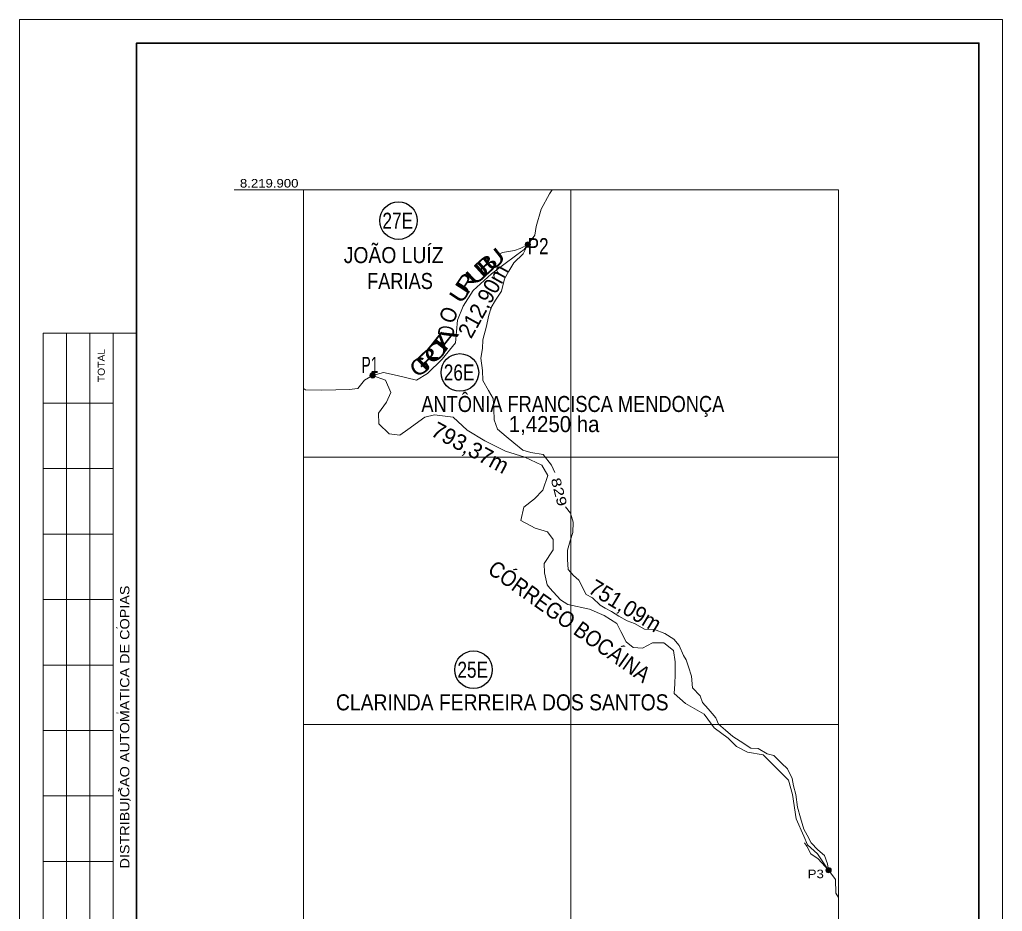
# Model space of a CAD drawing. Extents: x 253235 to 254153, y 8218760 to 8220059.
# Drawn here: x 253235 to 254153, y 8219225 to 8220059 of the extents above; entities that cross this region are included whole.
import ezdxf
from ezdxf.enums import TextEntityAlignment as Align

# ---------------------------------------------------------------- set-up
doc = ezdxf.new("R2010")
doc.units = 0
doc.header["$LTSCALE"] = 4.7
for name, color, linetype, lineweight in [('1', 7, 'Continuous', 13), ('2', 7, 'Continuous', 13), ('3', 7, 'Continuous', 13), ('34', 7, 'Continuous', 25), ('37', 7, 'Continuous', 13), ('6', 7, 'Continuous', 13)]:
    doc.layers.add(name, color=color, linetype=linetype, lineweight=lineweight)
for name, color, linetype in [('31', 7, 'Continuous'), ('32', 7, 'Continuous'), ('33', 7, 'Continuous'), ('40', 7, 'Continuous')]:
    doc.layers.add(name, color=color, linetype=linetype)

msp = doc.modelspace()

# ---------------------------------------------------------------- hatches: boundary and pattern name
at = {"layer": '37'}
for points in [[(253712.175, 8219848.903, 1), (253707.175, 8219848.903, 1)], [(253567.05, 8219726.55, 1), (253562.05, 8219726.55, 1)], [(253993.305, 8219263.695, 1), (253988.305, 8219263.695, 1)]]:
    msp.add_hatch(color=256, dxfattribs=at).paths.add_polyline_path(points)

# ---------------------------------------------------------------- linework, layer by layer
at = {"layer": '1'}
for points in [[(253682.39, 8219839.93), (253685.96, 8219841.49), (253697.16, 8219843.28), (253702.54, 8219845.07), (253709.67, 8219848.9), (253705.22, 8219840.15), (253696.71, 8219831.64), (253691.78, 8219824.02), (253687.75, 8219816.85), (253685.01, 8219805.15), (253679.51, 8219797.02), (253675.28, 8219790.11), (253672.76, 8219781.57), (253671.12, 8219772.41), (253667.59, 8219759.73), (253667.15, 8219751.67), (253665.8, 8219742.71), (253667.15, 8219731.06), (253667.59, 8219721.66), (253672.97, 8219712.25), (253677.3, 8219704.87)], [(253677.3, 8219704.87), (253677.84, 8219694.95), (253678.06, 8219684.82), (253681.36, 8219676.17), (253689.47, 8219669.21), (253696.63, 8219663.31), (253704.84, 8219656.63), (253712.39, 8219654.24), (253724.04, 8219652.44), (253731.66, 8219642.59), (253734.77, 8219635.51)], [(253744.9, 8219603.58), (253749.47, 8219597.47), (253752.02, 8219589.12), (253751.68, 8219579.62), (253749.3, 8219571.84), (253746.68, 8219563.08), (253746.81, 8219554.29), (253747.44, 8219544.97), (253752.49, 8219539.33), (253757.41, 8219534.85), (253764.13, 8219521.41), (253769.96, 8219518.27), (253777.13, 8219511.55), (253782.05, 8219508.87), (253787.88, 8219505.73), (253794.6, 8219501.25), (253802.66, 8219496.77), (253809.38, 8219494.53), (253818.79, 8219489.15), (253828.19, 8219488.71), (253837.6, 8219485.12), (253846.11, 8219479.75), (253851.04, 8219473.92), (253855.07, 8219464.52), (253857.76, 8219460.48), (253860, 8219453.99), (253862.69, 8219445.03), (253863.59, 8219434.28), (253870.75, 8219426.66), (253872.99, 8219420.39), (253878.37, 8219414.57), (253881.95, 8219410.09), (253885.54, 8219406.05), (253888.01, 8219400.37), (253894.52, 8219394.72), (253901.25, 8219388.81), (253908.22, 8219384.2), (253918.24, 8219377.83), (253924.96, 8219377.38), (253933.47, 8219372.46), (253939.52, 8219370.89), (253946.69, 8219363.72), (253952.39, 8219358.31), (253956.78, 8219349.42), (253957.89, 8219342.66), (253960.13, 8219334.6), (253961.92, 8219322.51), (253964.61, 8219312.65), (253967.74, 8219301.9), (253970.76, 8219296.44), (253974.66, 8219289.37), (253980.82, 8219282.74), (253986.95, 8219277.41), (253989.69, 8219269.64), (253990.81, 8219263.69), (253980.99, 8219274.33), (253974.13, 8219279), (253970.43, 8219286.22), (253968.41, 8219289.11)]]:
    msp.add_lwpolyline(points, dxfattribs=at)
at = {"layer": '2'}
for points in [[(253500, 8219714.11), (253501.75, 8219712.98), (253516.36, 8219712.68), (253530.15, 8219713.11), (253542.59, 8219713.23), (253550.59, 8219714.36), (253556.96, 8219722.03), (253564.55, 8219726.55), (253576.53, 8219721.92), (253581.62, 8219710.57), (253577.38, 8219701.61), (253570, 8219691.21), (253570.43, 8219681.14), (253579.94, 8219671.96), (253589.94, 8219670.72)], [(253589.94, 8219670.72), (253597.46, 8219675.94), (253613.32, 8219687.48), (253622.37, 8219689.67), (253639.89, 8219687.34), (253652.92, 8219675.34), (253669.35, 8219665.22), (253688.84, 8219655.72), (253706.82, 8219650.16), (253722.86, 8219642.62), (253728.5, 8219632.95), (253723.64, 8219619.23), (253715.82, 8219611.09), (253706.01, 8219603.33), (253703.21, 8219590.9), (253716.55, 8219583.66), (253727.9, 8219580.14), (253733.26, 8219572.84), (253733.3, 8219563.3), (253724.8, 8219550.66), (253725.08, 8219541.88), (253727.64, 8219530.68), (253730.09, 8219527.51), (253740.25, 8219516.4), (253747.04, 8219512.11), (253767.41, 8219507.97), (253780.88, 8219501.97), (253792.88, 8219494.32), (253796.68, 8219487.08), (253801.57, 8219477.24), (253808.28, 8219472.08), (253816.87, 8219471.4), (253826.06, 8219476.39), (253836.73, 8219476.25), (253845.87, 8219469.06), (253847.49, 8219458.48), (253847.42, 8219446.83), (253847.06, 8219437.97), (253846.55, 8219428.9), (253857.19, 8219419.64), (253874.42, 8219409.7), (253883.98, 8219396.85), (253896.84, 8219387.06), (253904.75, 8219379.51), (253914.96, 8219374.18), (253929.58, 8219371.5), (253953.43, 8219347.88), (253956.96, 8219334.49), (253960.63, 8219311.78), (253967.8, 8219295.42), (253971.19, 8219287.36), (253980.41, 8219278.82), (253988.6, 8219266.7), (253997.26, 8219254.9), (253997.65, 8219242.24), (254000, 8219238.14)]]:
    msp.add_lwpolyline(points, dxfattribs=at)
at = {"layer": '3'}
for points in [[(253699.48, 8219839.21), (253706.19, 8219844.25), (253716.13, 8219857.52), (253717.32, 8219865.64), (253722.23, 8219881.9), (253729.93, 8219896.4), (253732.4, 8219900)], [(253564.55, 8219726.55), (253574.72, 8219729.2), (253587.46, 8219726.31), (253605.4, 8219722.05), (253615.96, 8219728.38), (253629.68, 8219741.53), (253641.99, 8219757.08), (253643.75, 8219778.16), (253649.12, 8219791.3), (253658.65, 8219805.91), (253675.75, 8219821.36), (253685.89, 8219829.35), (253699.48, 8219839.21)]]:
    msp.add_lwpolyline(points, dxfattribs=at)
at = {"layer": '34'}
for centre in [(253588.72, 8219871.241), (253646.086, 8219729.24), (253658.844, 8219451.204)]:
    msp.add_circle(centre, 17.6, dxfattribs=at)
at = {"layer": '37'}
for centre in [(253709.675, 8219848.903), (253564.55, 8219726.55), (253990.805, 8219263.695)]:
    msp.add_circle(centre, 2.5, dxfattribs=at)
at = {"layer": '6'}
for p, q in [((253435, 8219900), (254000, 8219900)), ((253500, 8219095), (253500, 8219900)), ((253750, 8219150), (253750, 8219900)), ((254000, 8219095), (254000, 8219900)), ((253256.41, 8219766.08), (253343.91, 8219766.08)), ((253256.41, 8219766.08), (253256.41, 8219022.38)), ((253278.31, 8219766.08), (253278.31, 8219022.38)), ((253300.11, 8219022.38), (253300.11, 8219766.08)), ((253322.01, 8219766.08), (253322.01, 8219022.38)), ((253256.41, 8219700.48), (253322.01, 8219700.48)), ((253500, 8219650), (254000, 8219650)), ((253256.41, 8219639.28), (253322.01, 8219639.28)), ((253256.41, 8219578.08), (253322.01, 8219578.08)), ((253256.41, 8219516.78), (253322.01, 8219516.78)), ((253326.01, 8219490.18), (253324.71, 8219490.68)), ((253256.41, 8219455.48), (253322.01, 8219455.48)), ((253326.51, 8219410.48), (253325.11, 8219410.88)), ((253256.41, 8219394.28), (253322.01, 8219394.28)), ((253500, 8219400), (254000, 8219400)), ((253256.41, 8219333.08), (253322.01, 8219333.08)), ((253337.11, 8219329.48), (253338.21, 8219328.88)), ((253256.41, 8219271.78), (253322.01, 8219271.78))]:
    msp.add_line(p, q, dxfattribs=at)
msp.add_lwpolyline([(253234.51, 8218759.88), (254153.31, 8218759.88), (254153.31, 8220059.28), (253234.51, 8220059.28)], close=True, dxfattribs=at)
at = {"layer": '6', "lineweight": 35}
msp.add_lwpolyline([(253343.91, 8218781.78), (254131.41, 8218781.78), (254131.41, 8220037.38), (253343.91, 8220037.38)], close=True, dxfattribs=at)
at = {"layer": '6'}
msp.add_spline([(253327.21, 8219337.28), (253326.91, 8219338.28), (253327.51, 8219338.88), (253327.71, 8219339.58), (253327.31, 8219340.38)], degree=3, dxfattribs=at)

# ---------------------------------------------------------------- texts
at = {"layer": '1', "width": 0.85}
msp.add_text('FARIAS', height=15, dxfattribs=at).set_placement((253590.075, 8219807.28), align=Align.CENTER)
at = {"layer": '1', "width": 1.35}
msp.add_text('829', height=9, rotation=284.747, dxfattribs=at).set_placement((253734.453, 8219616.355), align=Align.CENTER)
at = {"layer": '31', "width": 0.95}
msp.add_text('212,90m', height=15, rotation=60.902, dxfattribs=at).set_placement((253674.672, 8219792.468), align=Align.CENTER)
msp.add_text('1,4250 ha', height=15, dxfattribs=at).set_placement((253734.21, 8219673.46), align=Align.CENTER)
at = {"layer": '32'}
msp.add_text('793,37m', height=15, rotation=331.83, dxfattribs=at).set_placement((253652.309, 8219652.256), align=Align.CENTER)
at = {"layer": '32', "width": 0.95}
msp.add_text('751,09m', height=15, rotation=328.859, dxfattribs=at).set_placement((253796.836, 8219504.628), align=Align.CENTER)
at = {"layer": '33'}
for s, width, p in [('JOÃO LUÍZ', 0.9, (253584.185, 8219831.54)), ('ANTÔNIA FRANCISCA MENDONÇA', 0.85, (253751.71, 8219692.27)), ('CLARINDA FERREIRA DOS SANTOS', 0.9, (253685.735, 8219413.16))]:
    msp.add_text(s, height=15, dxfattribs=dict(at, width=width)).set_placement(p, align=Align.CENTER)
at = {"layer": '34', "width": 0.8}
for s, p in [('27E', (253587.98, 8219863.68)), ('26E', (253645.35, 8219721.73)), ('25E', (253658.1, 8219443.66))]:
    msp.add_text(s, height=15, dxfattribs=at).set_placement(p, align=Align.CENTER)
at = {"layer": '37'}
for s, height, width, p in [('P2', 15, 0.8, (253719.23, 8219839.88)), ('P1', 15, 0.65, (253562.015, 8219728.86)), ('P3', 8, 1.15, (253978.885, 8219256.16))]:
    msp.add_text(s, height=height, dxfattribs=dict(at, width=width)).set_placement(p, align=Align.CENTER)
at = {"layer": '40'}
for s, rotation, width, p in [('U', 38.237, 1.4, (253682.473, 8219829.192)), ('U', 42.098, 1.5, (253667.607, 8219816.697)), ('B', 42.098, 1.65, (253675.257, 8219823.617)), ('R', 56.884, 1.25, (253658.146, 8219808.802)), ('U', 56.884, 1.25, (253652.516, 8219800.162)), ('O', 67.771, 0.9, (253642.469, 8219780.293)), ('D', 85.227, 0.65, (253640.855, 8219767.576)), ('T', 51.633, 1.75, (253634.149, 8219750.405)), ('A', 51.633, 1.65, (253638.803, 8219756.27)), ('R', 43.785, 1.55, (253621.675, 8219736.626)), ('O', 43.785, 1.45, (253628.775, 8219743.436)), ('G', 30.94, 1.15, (253612.604, 8219728.694)), ('CÓRREGO BOCÁINA', 324.557, 0.9, (253744.191, 8219490.245))]:
    msp.add_text(s, height=15, rotation=rotation, dxfattribs=dict(at, width=width)).set_placement(p, align=Align.CENTER)
at = {"layer": '6', "width": 1.15}
msp.add_text('8.219.900', height=8, dxfattribs=at).set_placement((253467.81, 8219902.21), align=Align.CENTER)
at = {"layer": '6'}
for s, height, width, p in [('TOTAL', 6.562, 1.1, (253314.11, 8219720.17)), ('DISTRIBUICAO AUTOMATICA DE COPIAS', 8.75, 1.15, (253337.11, 8219265.27))]:
    msp.add_text(s, height=height, rotation=90, dxfattribs=dict(at, width=width)).set_placement(p)

doc.saveas('drawing.dxf')
